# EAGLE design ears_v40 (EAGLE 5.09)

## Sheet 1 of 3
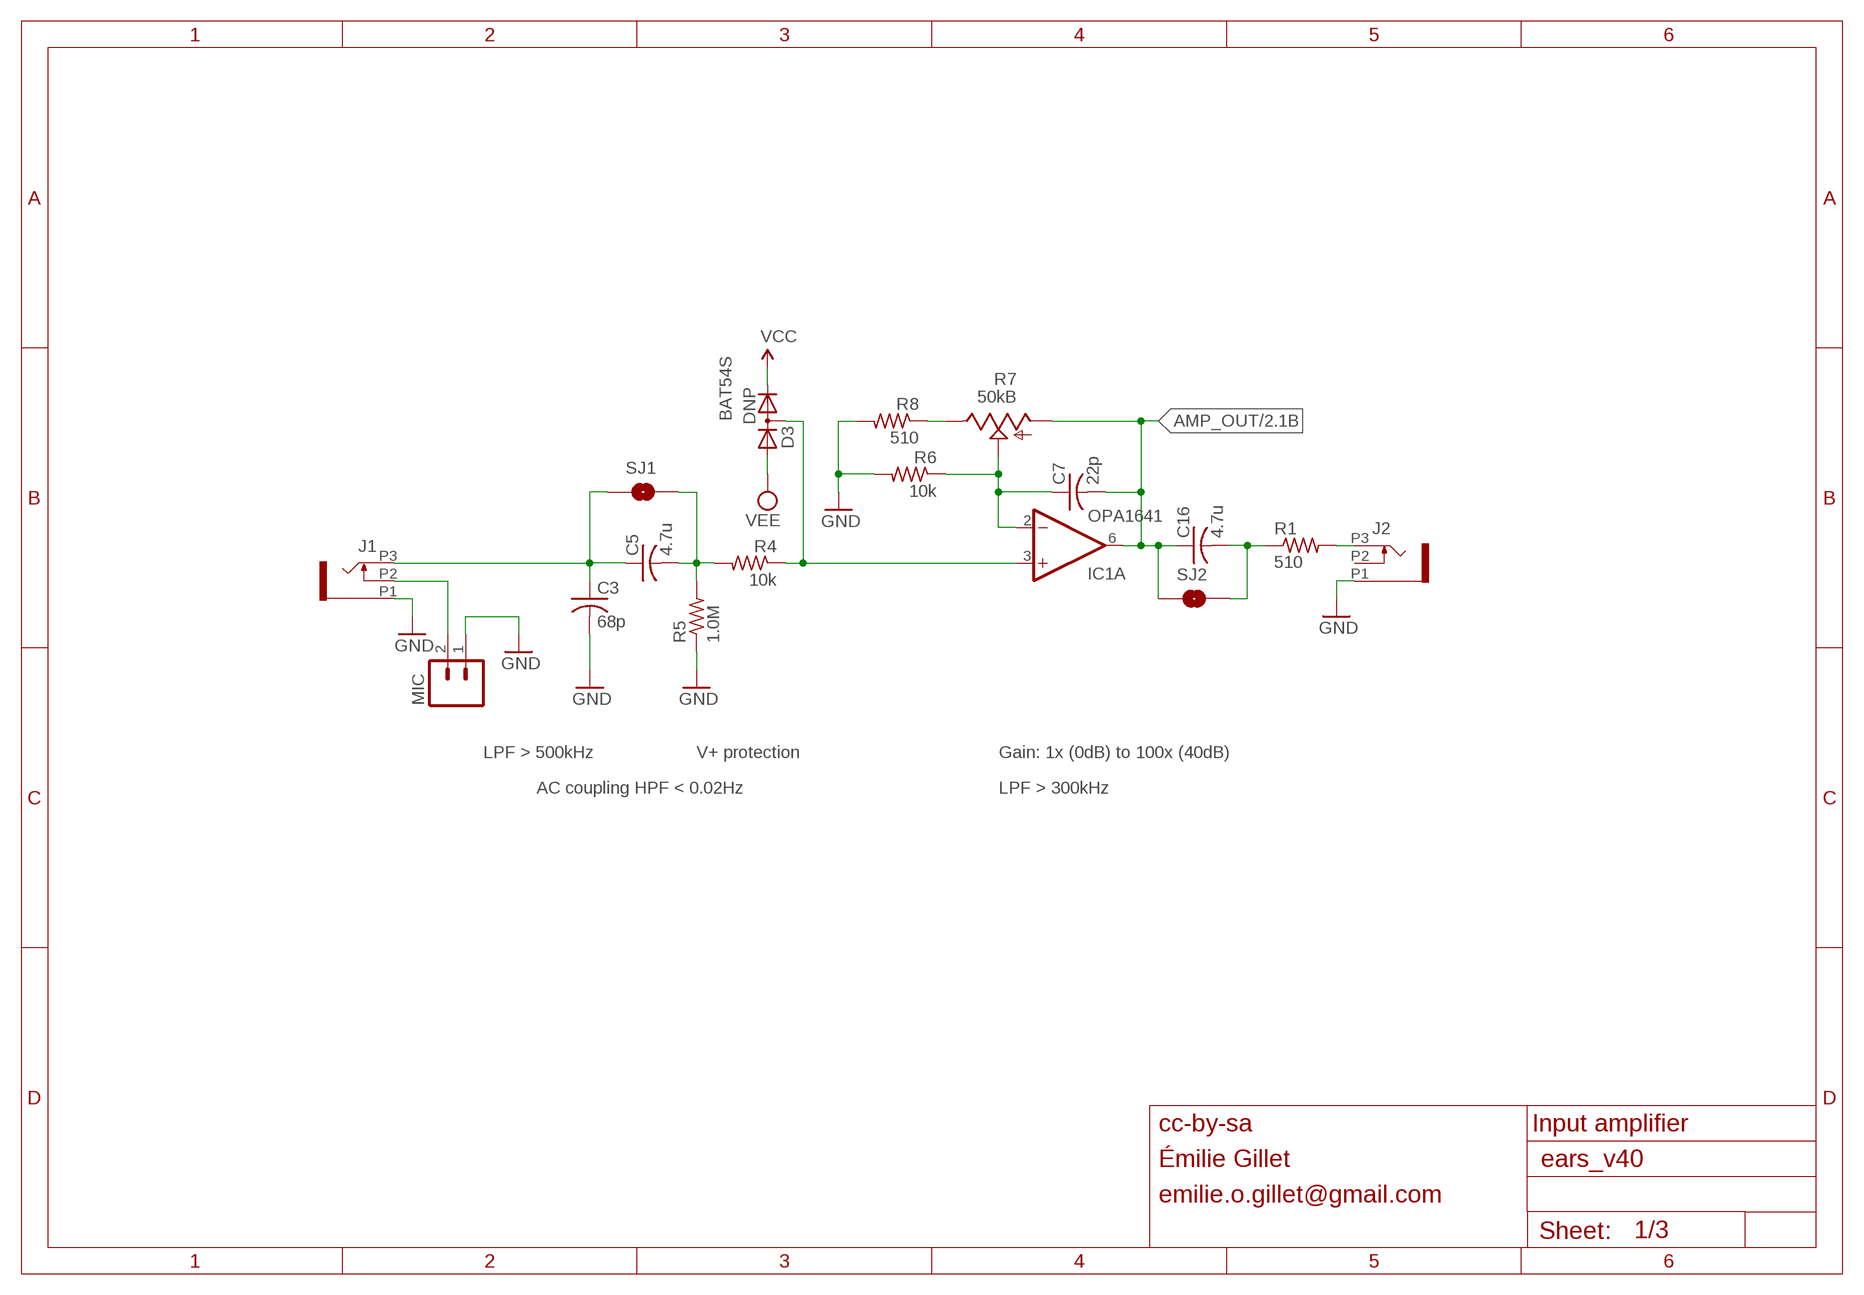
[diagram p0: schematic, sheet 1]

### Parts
C3  68p  C-USC0402  [C0402]
C5  4.7u  C-USC0603  [C0603]
C7  22p  C-USC0402  [C0402]
C16  4.7u  C-USC0603  [C0603]
D3  DNP  DIODE_2CACA-SOT23  [SOT23]
IC1  OPA1641  [MSOP8]
J1  PJ301_THONKICONN6  [WQP_PJ_301M6]
J2  PJ301_THONKICONN6  [WQP_PJ_301M6]
MIC  M02TINY  [1X02_TINY]
R1  510  R-US_R0402  [R0402]
R4  10k  R-US_R0402  [R0402]
R5  1.0M  R-US_R0402  [R0402]
R6  10k  R-US_R0402  [R0402]
R7  50kB  POT_USVERTICAL_PS  [ALPS_POT_VERTICAL_PS]
R8  510  R-US_R0402  [R0402]
SJ1  SOLDERJUMPERNC  [SJ_2S]
SJ2  SOLDERJUMPERNC  [SJ_2S]

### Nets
AMP_OUT: C7.2 C16.1 IC1.6(A:OUT) R7.P$3(A) SJ2.1 ; also sheet 2
GND: C3.2 J1.P1 J2.P1 MIC.1 R5.1 R6.2 R8.2 ; also sheet 2,3
N$2: D3.3(AC) IC1.3(A:+IN) R4.1
N$3: J2.P3 R1.2
N$4: C3.1 C5.1 J1.P3 SJ1.1
N$7: J1.P2 MIC.2
N$9: C7.1 IC1.2(A:-IN) R6.1 R7.P$2(S)
N$10: C5.2 R4.2 R5.2 SJ1.2
N$13: R7.P$1(E) R8.1
N$15: C16.2 R1.1 SJ2.2
VCC: D3.2(C) ; also sheet 2,3
VEE: D3.1(A) ; also sheet 2,3
Unconnected: J2.P2

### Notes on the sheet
- BAT54S
- LPF > 500kHz | V+ protection | Gain: 1x (0dB) to 100x (40dB)
- AC coupling HPF < 0.02Hz | LPF > 300kHz
- cc-by-sa | Input amplifier
- Émilie Gillet
- emilie.o.gillet@gmail.com

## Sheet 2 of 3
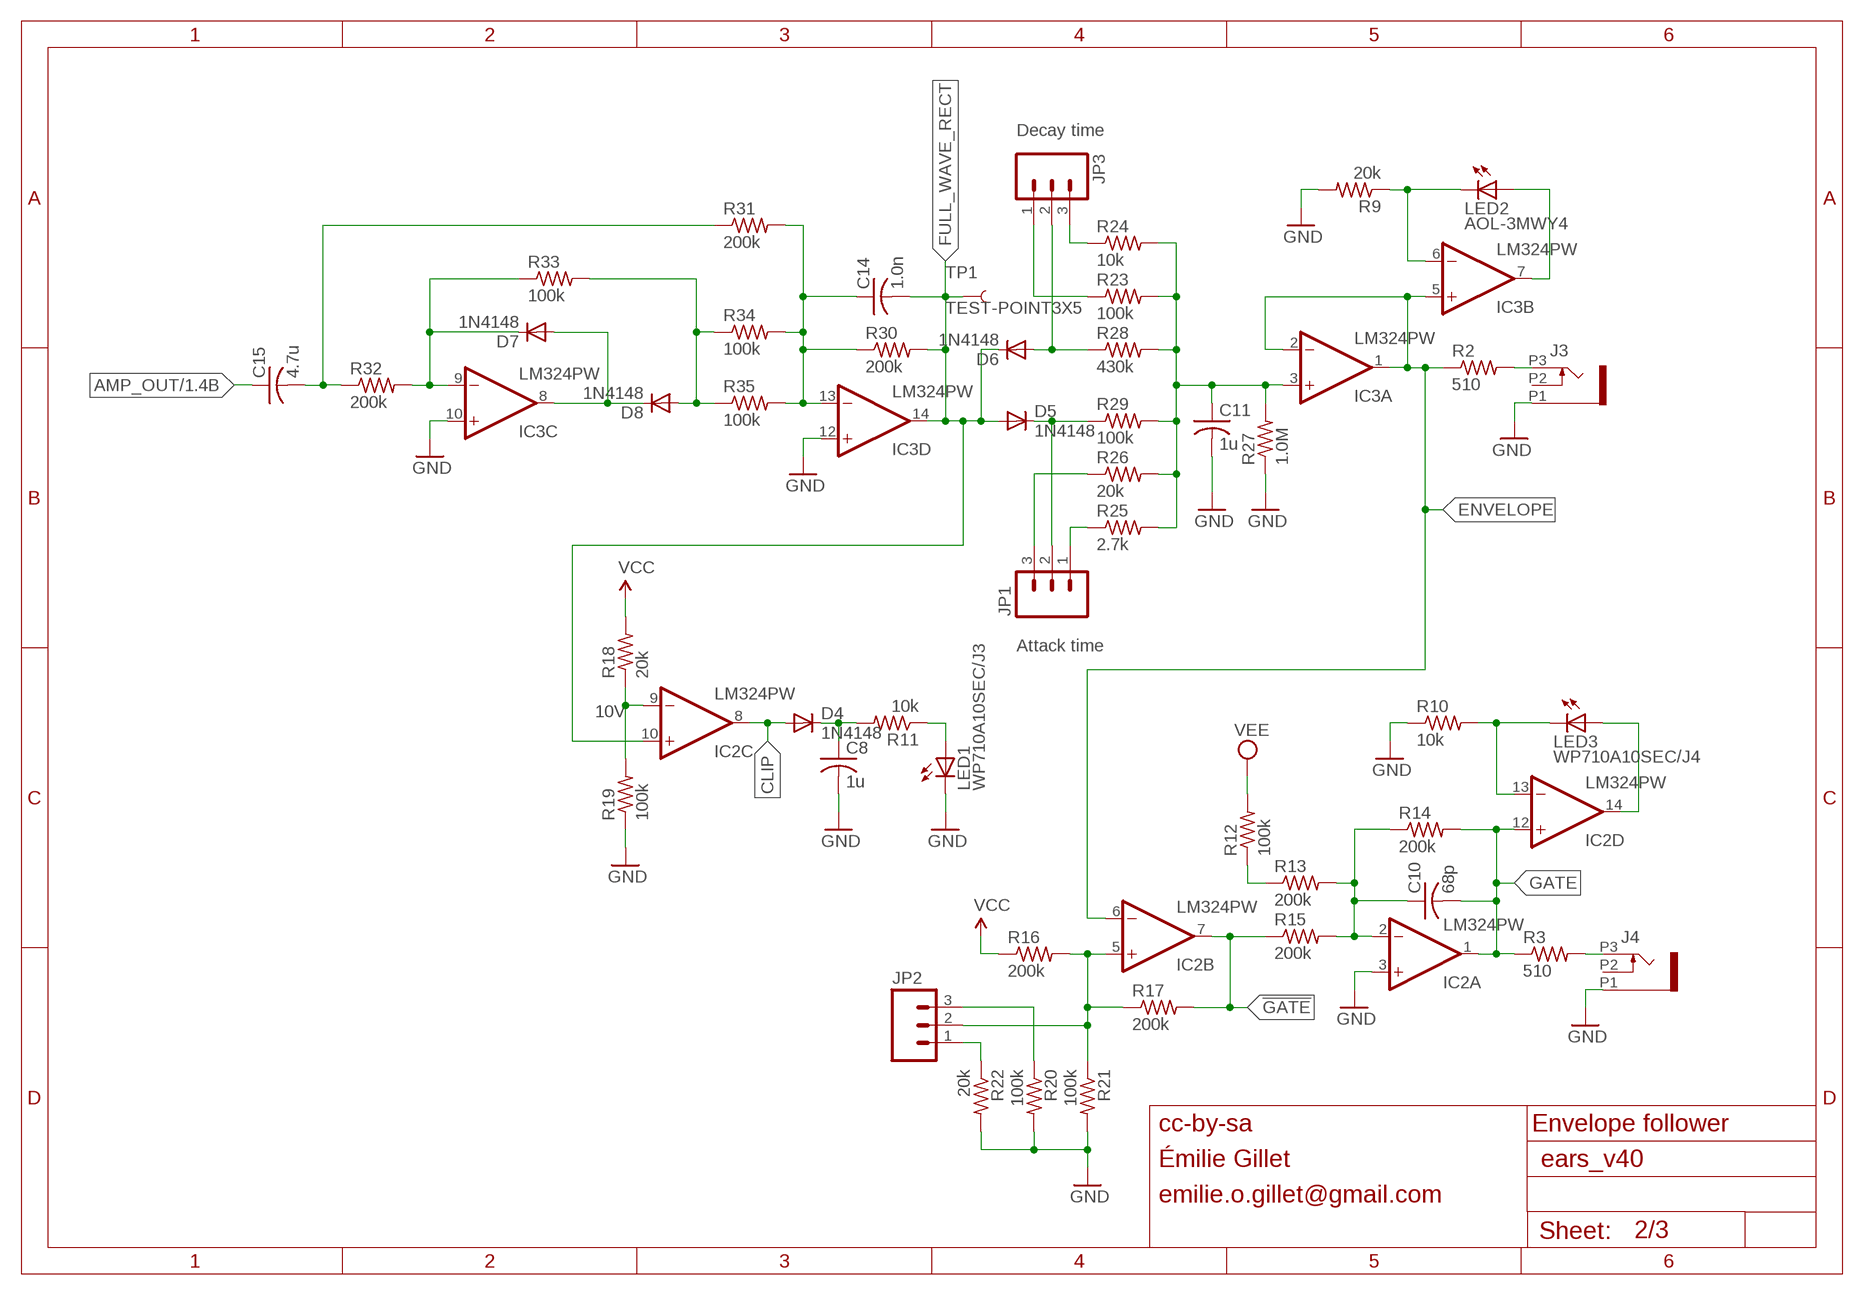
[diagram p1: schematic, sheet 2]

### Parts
C8  1u  C-USC0402  [C0402]
C10  68p  C-USC0402  [C0402]
C11  1u  C-USC0402  [C0402]
C14  1.0n  C-USC0402  [C0402]
C15  4.7u  C-USC0603  [C0603]
D4  1N4148  DIODE-SOD523  [SOD523]
D5  1N4148  DIODE-SOD523  [SOD523]
D6  1N4148  DIODE-SOD523  [SOD523]
D7  1N4148  DIODE-SOD523  [SOD523]
D8  1N4148  DIODE-SOD523  [SOD523]
IC2  LM324PW  [TSSOP14]
IC3  LM324PW  [TSSOP14]
J3  PJ301_THONKICONN6  [WQP_PJ_301M6]
J4  PJ301_THONKICONN6  [WQP_PJ_301M6]
JP1  M03PTH  [1X03]
JP2  M03PTH  [1X03]
JP3  M03PTH  [1X03]
LED1  WP710A10SEC/J3  LED3MM  [LED3MM]
LED2  AOL-3MWY4  LED3MM  [LED3MM]
LED3  WP710A10SEC/J4  LED3MM  [LED3MM]
R2  510  R-US_R0402  [R0402]
R3  510  R-US_R0402  [R0402]
R9  20k  R-US_R0402  [R0402]
R10  10k  R-US_R0402  [R0402]
R11  10k  R-US_R0402  [R0402]
R12  100k  R-US_R0402  [R0402]
R13  200k  R-US_R0402  [R0402]
R14  200k  R-US_R0402  [R0402]
R15  200k  R-US_R0402  [R0402]
R16  200k  R-US_R0402  [R0402]
R17  200k  R-US_R0402  [R0402]
R18  20k  R-US_R0402  [R0402]
R19  100k  R-US_R0402  [R0402]
R20  100k  R-US_R0402  [R0402]
R21  100k  R-US_R0402  [R0402]
R22  20k  R-US_R0402  [R0402]
R23  100k  R-US_R0402  [R0402]
R24  10k  R-US_R0402  [R0402]
R25  2.7k  R-US_R0402  [R0402]
R26  20k  R-US_R0402  [R0402]
R27  1.0M  R-US_R0402  [R0402]
R28  430k  R-US_R0402  [R0402]
R29  100k  R-US_R0402  [R0402]
R30  200k  R-US_R0402  [R0402]
R31  200k  R-US_R0402  [R0402]
R32  200k  R-US_R0402  [R0402]
R33  100k  R-US_R0402  [R0402]
R34  100k  R-US_R0402  [R0402]
R35  100k  R-US_R0402  [R0402]
TP1  TEST-POINT3X5  [PAD.03X.05]

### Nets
!GATE: IC2.7(B:OUT) R15.1 R17.2
AMP_OUT: C15.1 ; also sheet 1
AMP_OUT_AC: C15.2 R31.1 R32.1
CLIP: D4.A IC2.8(C:OUT)
ENVELOPE: IC2.6(B:-IN) IC3.1(A:OUT) IC3.2(A:-IN) IC3.5(B:+IN) R2.1
FULL_WAVE_RECT: C14.2 D5.A D6.C IC2.10(C:+IN) IC3.14(D:OUT) R30.2 TP1.P$1
GATE: C10.2 IC2.1(A:OUT) IC2.12(D:+IN) R3.1 R14.2
GND: C8.2 C11.2 IC2.3(A:+IN) IC3.10(C:+IN) IC3.12(D:+IN) J3.P1 J4.P1 LED1.K(C) R9.2 R10.1 R19.1 R20.2 R21.2 R22.2 R27.1 ; also sheet 1,3
N$5: D7.A D8.C IC3.8(C:OUT)
N$8: C10.1 IC2.2(A:-IN) R13.2 R14.1 R15.2
N$11: D7.C IC3.9(C:-IN) R32.2 R33.1
N$12: D8.A R33.2 R34.1 R35.1
N$14: C14.1 IC3.13(D:-IN) R30.1 R31.2 R34.2 R35.2
N$16: J3.P3 R2.2
N$17: IC3.6(B:-IN) LED2.K(C) R9.1
N$18: D5.C JP1.2 R29.1
N$19: C11.1 IC3.3(A:+IN) R23.2 R24.2 R25.2 R26.2 R27.2 R28.2 R29.2
N$21: JP3.3 R24.1
N$23: JP3.1 R23.1
N$24: D6.A JP3.2 R28.1
N$25: JP1.1 R25.1
N$26: JP1.3 R26.1
N$27: IC2.9(C:-IN) R18.1 R19.2
N$28: C8.1 D4.C R11.2
N$30: IC3.7(B:OUT) LED2.A
N$31: LED1.A R11.1
N$32: J4.P3 R3.2
N$33: IC2.5(B:+IN) JP2.2 R16.2 R17.1 R21.1
N$35: JP2.1 R22.1
N$36: JP2.3 R20.1
N$37: IC2.13(D:-IN) LED3.K(C) R10.2
N$38: IC2.14(D:OUT) LED3.A
N$39: R12.1 R13.1
VCC: R16.1 R18.2 ; also sheet 1,3
VEE: R12.2 ; also sheet 1,3
Unconnected: J3.P2 J4.P2

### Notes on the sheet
- Decay time
- Attack time
- 10V
- cc-by-sa | Envelope follower
- Émilie Gillet
- emilie.o.gillet@gmail.com

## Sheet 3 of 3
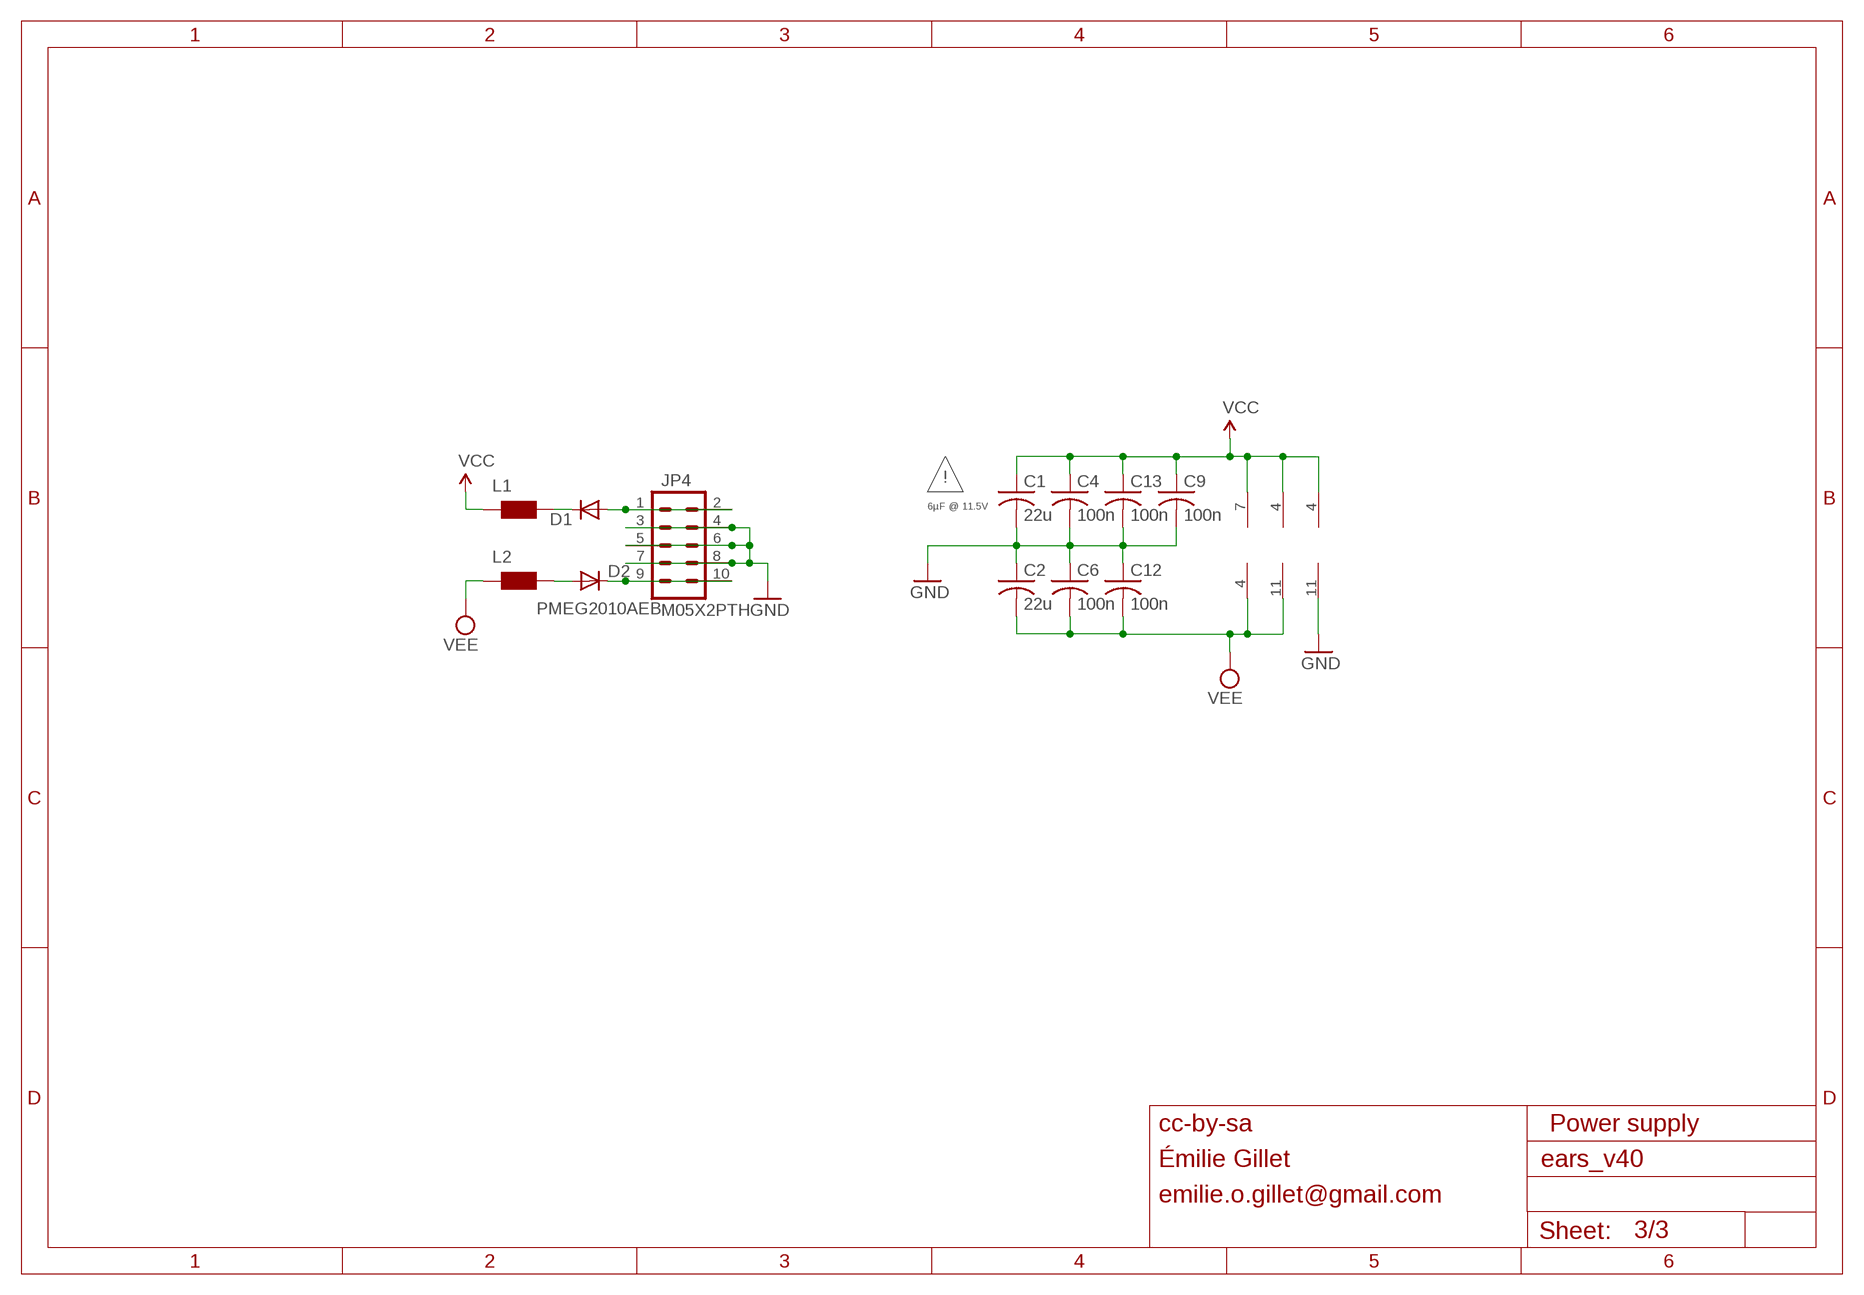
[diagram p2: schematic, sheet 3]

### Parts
C1  22u  C-USC1206  [C1206]
C2  22u  C-USC1206  [C1206]
C4  100n  C-USC0402  [C0402]
C6  100n  C-USC0402  [C0402]
C9  100n  C-USC0402  [C0402]
C12  100n  C-USC0402  [C0402]
C13  100n  C-USC0402  [C0402]
D1  PMEG2010AEB  DIODE-SOD523  [SOD523]
D2  PMEG2010AEB  DIODE-SOD523  [SOD523]
JP4  M05X2PTH  [AVR_ICSP]
L1  WE-CBF_0603  [0603]
L2  WE-CBF_0603  [0603]

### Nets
GND: C1.2 C2.1 C4.2 C6.1 C9.2 C12.1 C13.2 IC2.11(P:V-) JP4.3 JP4.4 JP4.5 JP4.6 JP4.7 JP4.8 ; also sheet 1,2
N$6: D1.A JP4.1 JP4.2
N$20: D2.C JP4.9 JP4.10
N$22: D1.C L1.2
N$44: D2.A L2.2
VCC: C1.1 C4.1 C9.1 C13.1 IC1.7(V+) IC2.4(P:V+) IC3.4(P:V+) L1.1 ; also sheet 1,2
VEE: C2.2 C6.2 C12.2 IC1.4(V-) IC3.11(P:V-) L2.1 ; also sheet 1,2

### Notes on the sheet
- !
- 6µF @ 11.5V
- cc-by-sa | Power supply
- Émilie Gillet
- emilie.o.gillet@gmail.com

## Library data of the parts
C1-C16 = rcl:C-US: CAPACITOR, American symbol
D1 D2 D4-D8 = diode:DIODE-: DIODE
D3 = diode:DIODE_2CACA-: 2 Diodes - Cathode-Anode|Cathode-Anode
IC1 = og-ics:OPA1641
IC2 IC3 = og-ics:LM324: OP AMP
J1-J4 = og-pj301:PJ301_THONKICONN
JP1-JP3 = SparkFun:M03: Header 3 Standard 3-pin 0.1" header. Use with straight break away headers (SKU : PRT-00116), right angle break away headers (PRT-00553), swiss pins (PRT-00743), machine pins (PRT-00117), and female headers (PRT-00115). Molex polarized connector foot print use with SKU : PRT-08232 with associated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
JP4 = og-header:M05X2: Header 5x2 Standard 10-pin dual row 0.1" header. Commonly used with AVR-ISP. Use with Spark Fun Electronics SKU: PRT-00778
L1 L2 = wuerth-elektronik:WE-CBF: SMD EMI Suppression Ferrite Beads
LED1-LED3 = led:LED: LED
MIC = og-header:M02: Header 2
R1-R6 R8-R35 = rcl:R-US_: RESISTOR, American symbol
R7 = og-pots:POT_US
SJ1 SJ2 = SparkFun:SOLDERJUMPER: Solder Jumper
TP1 = SparkFun:TEST-POINT

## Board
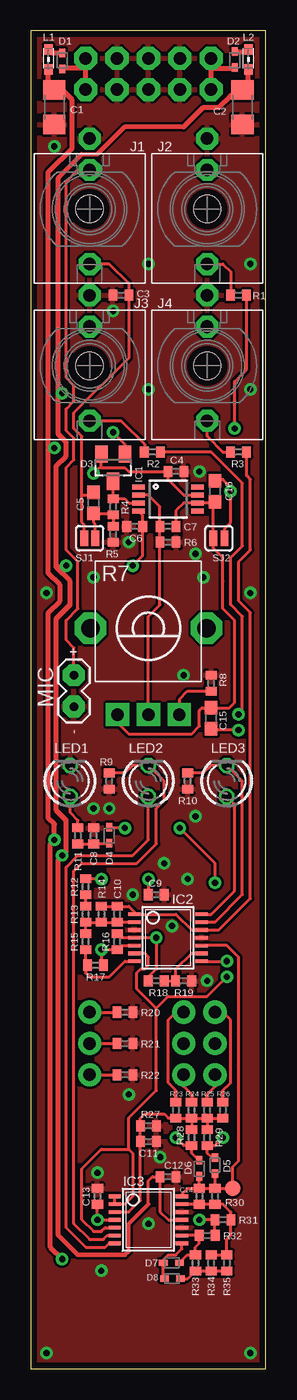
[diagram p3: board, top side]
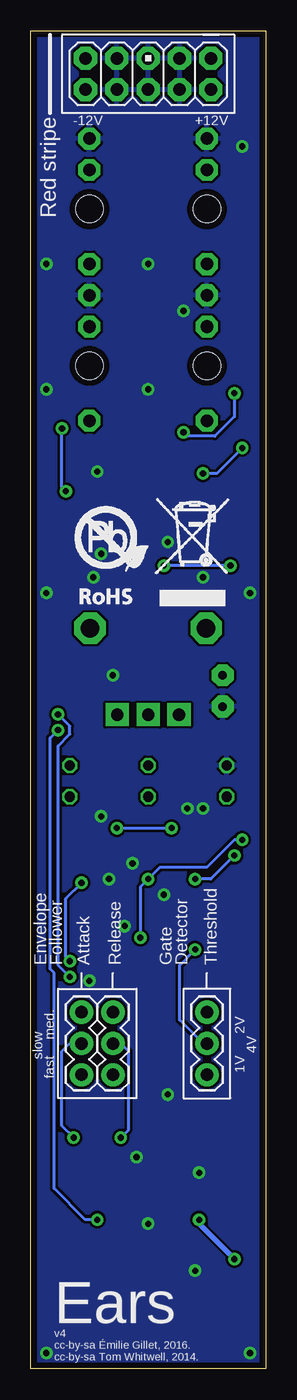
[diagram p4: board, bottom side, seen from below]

Size 19.03 x 108.43 mm. Coordinates in mm from the lower left corner, seen from the top.
Outline: 0,0 19.03,0 19.03,108.43 0,108.43 0,0
Copper layers (1*16): Top 0.035mm / dielectric 1.5mm / Bottom 0.035mm
Design rules "PCBCart-Standard *": minimum track width 8mil, minimum drill 0.4mm, track to track 8mil, track to pad 8mil, pad to pad 8mil, via to via 8mil, smd to smd 8mil, copper to edge 20mil, drill to drill 8mil, minimum pad ring 8mil, minimum via ring 10mil, stop-mask expansion 3mil, vias tented up to drill 25mil, thermal gap 8mil

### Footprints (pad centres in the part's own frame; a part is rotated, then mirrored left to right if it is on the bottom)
C1206 = smd 1.6 x 1.8: 1 -1.4,0; 2 1.4,0
C0402 = smd 0.7 x 0.9: 1 -0.65,0; 2 0.65,0
C0603 = smd 1.1 x 1: 1 -0.85,0; 2 0.85,0
SOD523 = smd 0.7 x 0.5: A 0.7,0; C -0.6,0
SOT23 = smd 1 x 1.4: 1 -0.95,-1.1; 2 0.95,-1.1; 3 0,1.1
MSOP8 = smd 0.41 x 1.02: 1 -0.975,-2.4; 2 -0.325,-2.4; 3 0.325,-2.4; 4 0.975,-2.4; 5 0.975,2.4; 6 0.325,2.4; 7 -0.325,2.4; 8 -0.975,2.4
TSSOP14 = smd 0.305 x 0.991: 1 -1.905,-2.718; 2 -1.27,-2.718; 3 -0.635,-2.718; 4 0,-2.718; 5 0.635,-2.718; 6 1.27,-2.718; 7 1.905,-2.718; 8 1.905,2.718; 9 1.27,2.718; 10 0.635,2.718; 11 0,2.718; 12 -0.635,2.718; 13 -1.27,2.718; 14 -1.905,2.718
WQP_PJ_301M6 = drill 1.016 pad 1.778 octagon: P1 0,-5.715; P2 0,-3.175; P3 0,4.445 | hole 2.2: 0,0
1X03 = drill 1.016 pad 1.88 round: 1 0,0; 2 2.54,0; 3 5.08,0
AVR_ICSP = drill 1.016 pad 1.88 octagon: 1 -1.27,5.08; 2 1.27,5.08; 3 -1.27,2.54; 4 1.27,2.54; 5 -1.27,0; 6 1.27,0; 7 -1.27,-2.54; 8 1.27,-2.54; 9 -1.27,-5.08; 10 1.27,-5.08
0603 = smd 0.85 x 0.7: 1 -0.9,0; 2 0.7,0
LED3MM = drill 0.813 octagon: A -1.27,0; K 1.27,0
1X02_TINY = drill 0.7 pad 1.778 octagon: 1 0,0; 2 2.54,0
R0402 = smd 0.7 x 0.9: 1 -0.65,0; 2 0.65,0
ALPS_POT_VERTICAL_PS = drill 1 pad 1.88 square: P$1 -2.5,7; P$2 0,7; P$3 2.5,7 | drill 1.5 pad 2.54 octagon: P$4 -4.7,0; P$5 4.7,0
SJ_2S = smd 0.635 x 1.27: 1 -0.45,0; 2 0.45,0
PAD.03X.05 = smd 1.27 x 1.27: P$1 0,0

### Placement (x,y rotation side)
C1  1.91,102.23 270 top
C2  17.14,102.23 90 top
C3  7.3,87 180 top
C4  11.75,72.71 0 top
C5  5.08,70.17 270 top
C6  8.41,68.26 0 top
C7  11.11,68.26 0 top
C8  5.08,43.18 90 top
C9  10.16,38.42 0 top
C10  6.99,36.83 90 top
C11  9.53,18.41 0 top
C12  11.11,15.56 180 top
C13  5.4,13.97 90 top
C14  13.65,13.97 90 top
C15  14.61,52.7 270 top
C16  14.92,71.12 90 top
D1  2.54,106.05 270 top
D2  16.51,106.05 90 top
D3  6.67,73.03 180 top
D4  6.35,43.18 90 top
D5  14.92,16.51 270 top
D6  13.65,16.19 90 top
D7  11.43,8.57 180 top
D8  11.43,7.3 0 top
IC1  11.11,70.48 270 top
IC2  11.11,34.92 270 top
IC3  9.53,12.06 270 top
J1  4.76,93.98 180 top
J2  14.29,93.98 180 top
J3  4.76,81.28 180 top
J4  14.29,81.28 180 top
JP1  14.92,23.81 90 bottom
JP2  4.76,23.81 90 bottom
JP3  12.38,28.89 270 bottom
JP4  9.53,104.93 270 bottom
L1  1.43,106.2 90 top
L2  17.62,106.2 90 top
LED1  3.17,47.62 90 top
LED2  9.53,47.62 90 top
LED3  15.88,47.62 90 top
MIC  3.49,53.66 90 top
R1  16.83,87 180 top
R2  9.84,74.3 180 top
R3  16.83,74.3 180 top
R4  6.67,69.85 270 top
R5  6.67,67.63 90 top
R6  11.11,66.99 0 top
R7  9.53,60.01 180 top
R8  14.61,55.56 90 top
R9  6.35,47.62 270 top
R10  12.7,47.62 90 top
R11  3.81,43.18 270 top
R12  4.45,39.05 90 top
R13  4.45,36.83 270 top
R14  5.71,36.83 90 top
R15  4.45,34.61 90 top
R16  6.99,34.61 270 top
R17  5.24,32.7 180 top
R18  10.16,31.43 180 top
R19  12.38,31.43 180 top
R20  7.62,28.89 0 top
R21  7.62,26.35 0 top
R22  7.62,23.81 0 top
R23  11.75,20.95 270 top
R24  13.02,20.95 270 top
R25  14.29,20.95 270 top
R26  15.56,20.95 270 top
R27  9.53,19.68 180 top
R28  13.02,18.73 90 top
R29  14.29,18.73 90 top
R30  14.92,13.97 90 top
R31  15.56,12.06 0 top
R32  14.29,10.79 180 top
R33  13.34,8.57 270 top
R34  14.61,8.57 90 top
R35  15.88,8.57 90 top
SJ1  4.76,67.31 0 top
SJ2  15.24,67.31 0 top
TP1  16.35,14.61 0 top
U$2  [ROHS]  16.35,61.28 0 bottom

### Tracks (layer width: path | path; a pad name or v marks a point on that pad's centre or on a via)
!GATE
  Top 0.254: R15.1 4.45,32.85 R17.2 4.45,32.56 4.45,32.07 4.76,31.75 6.35,31.75 7.62,33.02 IC2.7
AMP_OUT
  Top 0.254: R7.P$3 6.99,52.97 6.99,52.39 7.94,51.44 13.02,51.44 13.65,52.07 13.65,53.34 13.87,53.55 C15.1 16.09,53.55 16.51,53.98 16.51,60.64 15.56,61.59 15.56,63.82 15.56,65.72 14.79,66.49 SJ2.1 14.79,70.14 14.82,70.17 | C7.2 11.75,68.28 11.75,69.53 12.38,70.16 IC1.6 14.82,70.17 | 14.82,70.17 C16.1
AMP_OUT_AC  (via drill 0.5)
  Top 0.254: R31.1 14.92,12.05 | R32.1 14.91,10.82 R31.1 | R31.1 v13.65,12.06 | C15.2 14.71,51.75 v16.83,51.75
  Bottom 0.254: v16.83,51.75 17.46,51.12 17.46,32.38 17.14,32.07 17.14,14.61 14.61,12.06 v13.65,12.06
CLIP  (via drill 0.5)
  Top 0.254: IC2.8 v15.88,33.02 | D4.A 6.42,43.81 v7.62,43.81 | v12.06,43.81 14.92,40.96 v14.92,39.37
  Bottom 0.254: v15.88,33.02 16.19,33.34 16.19,38.1 v14.92,39.37 | v12.06,43.81 v7.62,43.81
ENVELOPE  (via drill 0.5)
  Top 0.254: 6.67,11.43 IC3.5 6.03,11.43 5.71,11.11 5.08,11.11 4.13,12.06 4.13,16.19 5.71,17.78 7.94,17.78 | v15.88,31.75 14.29,30.16 11.11,30.16 10.16,29.21 | IC2.6 9.21,33.66 9.53,33.34 9.53,32.7 9.21,32.38 8.89,32.38 8.57,32.07 8.57,30.8 10.16,29.21 | IC3.1 IC3.2 7.62,13.34 8.26,13.97 8.26,17.46 7.94,17.78 | v16.83,53.02 17.14,53.34 17.14,60.96 16.19,61.91 16.19,65.72 17.14,66.67 17.14,71.75 15.56,73.34 14.61,74.3 R2.1 | 7.94,17.78 7.94,20.32 10.16,22.54 10.16,29.21
  Bottom 0.254: v16.83,53.02 15.88,52.07 15.88,51.44 16.83,50.48 16.83,32.7 v15.88,31.75
FULL_WAVE_RECT
  Top 0.254: C14.2 13.64,14.61 12.7,14.61 12.24,14.15 IC3.14 | C14.2 R30.2 | C14.2 D6.C | R30.2 D5.A | R30.2 14.94,14.61 TP1.P$1 16.35,16.35 16.83,16.83 16.83,33.34 15.88,34.29 IC2.10
GATE
  Top 0.254: R14.2 C10.2 7,37.47 7.94,37.47 8.39,37.01 IC2.1 11.75,36.83 13.02,35.56 IC2.12 15.24,35.56 17.78,38.1 17.78,61.28 16.83,62.23 16.83,65.41 17.78,66.36 17.78,72.07 17.48,72.38 R3.1
GND  (via drill 0.5)
  other vias: 5.4,15.88 5.71,7.94 13.97,64.14 13.65,72.71 7.94,66.99 14.29,31.43 10.48,17.14 12.7,39.69 9.53,11.75 1.91,99.06 6.35,45.4 13.34,44.77 1.27,62.87 7.94,22.23 5.08,45.4 12.38,56.2 17.78,1.27 1.27,1.27 17.78,62.87 5.08,64.14 8.26,38.42 10.79,40.96 11.43,35.88 17.78,89.53 17.78,79.38 9.53,89.53 9.53,79.38 13.34,66.04 6.67,85.72
  pour Bottom: 0,108.43 0,0 19.05,0 19.05,108.43
  pour Top: 0,108.43 0,0 19.05,0 19.05,108.43
N$2
  Top 0.254: IC1.3 | IC1.3 7.94,70.17 7.61,70.5 R4.1 D3.3
N$3
  Top 0.254: J2.P3 15.56,89.53 16.18,88.92 R1.2
N$4
  Top 0.254: J1.P3 6.35,89.53 7.95,87.93 C3.1 7.95,81.93 3.49,77.47 3.49,76.2 4.13,75.56 4.13,70.8 | 4.13,70.8 4.13,68.58 4.31,68.39 SJ1.1 | C5.1 4.87,70.8 4.13,70.8
N$5
  Top 0.254: D8.C 10.73,7.4 D7.A 10.79,8.64 10.79,8.89 11.11,9.21 11.75,9.21 12.24,9.7 IC3.8
N$6
  Top 0.406: JP4.2 4.45,105.41 | 4.45,105.41 JP4.1 | D1.A 2.6,105.41 4.45,105.41
N$7
  Top 0.254: MIC.2 3.49,58.42 2.86,59.05 2.86,60.64 3.81,61.59 3.81,65.41 2.86,66.36 2.86,73.03 3.49,73.66 3.49,75.41 2.86,76.04 2.86,77.79 3.49,78.42 3.49,79.69 2.86,80.33 2.86,80.64 2.86,96.2 3.81,97.16 J1.P2
N$8
  Top 0.254: IC2.2 7,36.2 C10.1 R14.1 R13.2 R15.2
N$9
  Top 0.254: R7.P$2 9.53,60.96 10.46,61.9 R6.1 C7.1 10.46,69.86 9.53,70.8 IC1.2
N$10
  Top 0.254: SJ1.2 5.21,68.45 5.08,68.58 C5.2 6.55,69.32 R4.2 R5.2
N$11
  Top 0.254: IC3.9 R32.2 13.64,10.14 13.34,9.84 R33.1 12.68,9.22 D7.C
N$12
  Top 0.254: R35.1 R34.1 R33.2 13.32,7.92 12.7,7.3 D8.A
N$13
  Top 0.254: R7.P$1 12.06,53.05 12.06,54.29 12.69,54.91 R8.1
N$14
  Top 0.254: IC3.13 13.64,13.34 C14.1 R30.1 14.94,13.34 15.56,13.34 16.21,12.69 R31.2 16.21,10.81 15.88,10.48 R35.2 R34.2
N$15  (via drill 0.5)
  Top 0.254: C16.2 15.03,72.07 15.56,72.07 16.19,71.44 v16.19,71.12 16.19,68.58 15.69,68.08 SJ2.2 | v16.51,76.2 16.51,80.01 17.48,80.98 R1.1
  Bottom 0.254: v16.19,71.12 16.51,71.44 v16.51,76.2
N$16
  Top 0.254: 9.21,74.31 R2.2 9.21,74.31 | 9.21,74.31 9.21,74.93 7.3,76.83 J3.P3
N$17
  Top 0.254: IC3.6 6.19,10.79 5.87,10.48 4.76,10.48 3.49,11.75 3.49,40.32 4.13,40.96 8.57,40.96 10.16,42.55 10.16,45.4 10.79,46.04 10.79,47.62 LED2.K 8.26,48.9 7.62,48.26 6.37,48.26 R9.1
N$18  (via drill 0.5)
  Top 0.254: D5.C 14.64,17.11 14.29,17.46 R29.1 14.3,18.1 14.92,18.1 v15.56,18.73
  Bottom 0.254: v15.56,18.73 16.51,19.68 16.51,25.72 15.88,26.35 JP1.2
N$19
  Top 0.254: R24.2 R23.2 11.73,20.32 11.11,20.32 10.79,20.64 9.21,20.64 8.88,20.3 R27.2 C11.1 8.88,13.64 7.94,12.7 IC3.3 | R24.2 R28.2 | R24.2 R25.2 | R25.2 R26.2 | R25.2 R29.2
N$20
  Top 0.406: JP4.10 14.61,105.41 | 14.61,105.41 JP4.9 | D2.C 16.48,105.41 14.61,105.41
N$21
  Top 0.254: JP3.3 12.38,22.86 13.02,22.23 R24.1
N$22
  Top 0.406: L1.2 1.69,106.64 D1.C
N$23
  Top 0.254: JP3.1 11.75,28.89 11.11,28.26 11.11,23.18 11.75,22.54 R23.1
N$24  (via drill 0.5)
  Top 0.254: D6.A 13.59,16.89 13.02,17.46 R28.1 13,18.1 12.38,18.1 v11.75,18.73
  Bottom 0.254: v11.75,18.73 11.11,19.37 11.11,25.72 11.75,26.35 JP3.2
N$25
  Top 0.254: JP1.1 14.92,22.86 14.29,22.23 R25.1
N$26
  Top 0.254: JP1.3 15.56,28.89 16.19,28.26 16.19,23.18 15.56,22.54 R26.1
N$27
  Top 0.254: R18.1 R19.2 11.75,31.45 11.75,32.38 13.02,33.66 IC2.9
N$28
  Top 0.254: R11.2 C8.1 5.13,42.58 D4.C
N$30
  Top 0.254: IC3.7 6.35,10.16 6.03,9.84 4.45,9.84 2.86,11.43 2.86,40.64 3.81,41.59 8.26,41.59 9.53,42.86 LED2.A
N$31
  Top 0.254: LED1.A 3.17,45.09 3.81,44.45 R11.1
N$32
  Top 0.254: J4.P3 14.29,75.56 15.56,74.3 R3.2
N$33  (via drill 0.5)
  Top 0.254: JP2.2 R21.1 | IC2.5 7.32,34.29 R16.2 6.97,33.97 v5.71,33.97 5.71,32.88 R17.1
  Bottom 0.254: v5.71,33.97 6.99,32.7 6.99,28.26 5.08,26.35 JP2.2
N$35
  Top 0.254: JP2.1 R22.1
N$36
  Top 0.254: JP2.3 R20.1
N$37
  Top 0.254: IC2.13 14.92,36.2 17.14,38.42 17.14,47.62 LED3.K 14.61,48.9 13.97,48.26 12.71,48.26 R10.2
N$38
  Top 0.254: IC2.14 14.61,36.83 16.51,38.73 16.51,45.72 LED3.A
N$39
  Top 0.254: R13.1 R12.1
N$44
  Top 0.406: L2.2 17.46,106.75 D2.A
VCC  (via drill 0.5)
  Top 0.254: R16.1 7.32,34.92 IC2.4 v10.16,34.92 10.16,32.38 9.53,31.75 9.53,31.45 R18.2 | v9.53,39.69 9.51,39.67 C9.1 | IC3.4 v5.4,12.06 C13.1 | IC1.7 12.38,70.8 11.1,72.09 C4.1 7.94,72.71 7.62,73.03 5.71,73.03 | v5.08,72.55 5.56,73.03 5.71,73.03 | D3.2 5.71,73.03
  Top 0.406: L1.1 1.43,103.98 1.59,103.82 1.72,103.82 C1.1 2.54,103.64 3.33,102.84 3.33,98.9 1.43,97 1.43,74.61 | 1.43,74.61 v1.91,74.61 | 1.43,74.61 1.43,64.45 2.38,63.5 2.38,62.23 1.43,61.28 1.43,44.61 1.91,44.13 v1.91,42.86 1.59,42.55 1.59,9.84 v2.54,8.89
  Bottom 0.254: v1.91,74.61 3.97,72.55 4.13,72.55 v5.08,72.55 | v1.91,42.86 2.54,42.86 4.76,40.64 8.57,40.64 v9.53,39.69 10.16,39.05 v10.16,34.92
  Bottom 0.406: v2.54,8.89 5.4,11.75 v5.4,12.06
VEE  (via drill 0.5)
  Top 0.254: C12.2 10.48,15.57 | C12.2 10.48,15.54 | v5.71,39.69 5.7,39.7 R12.2 | v8.26,65.09 8.75,65.58 9.06,65.9 C6.2 | 2.06,65.09 v2.86,65.09 | 9.53,13.34 9.53,15.24 9.84,15.56 C12.2 | IC3.11 11.11,12.06 10.46,12.71 C12.2 | C6.2 8.89,68.44 | 2.22,79.06 v2.54,79.06 | IC1.4 9.06,69.16 C6.2 | v6.67,75.88 7.62,74.93 D3.1
  Top 0.305: 7.62,9.21 7.94,9.53 7.94,11.75 9.53,13.34 | 4.13,98.42 5.4,98.42
  Top 0.356: 3.81,9.21 7.62,9.21 | 2.22,96.52 4.13,98.42 | 5.4,98.42 7.62,100.65
  Top 0.381: 7.62,100.65 12.38,100.65 | 3.81,9.21 2.22,10.79
  Top 0.406: L2.1 17.62,103.98 17.46,103.82 17.33,103.82 C2.2 17.14,103.19 16.19,103.19 15.24,102.23 13.97,102.23 12.38,100.65 | 2.22,10.79 2.22,41.27 v2.54,41.59 2.86,41.91 2.86,44.45 2.06,45.24 2.06,60.8 3.17,61.91 3.17,63.82 2.06,64.93 2.06,65.09 2.06,73.18 2.86,73.98 2.86,75.09 2.22,75.72 2.22,79.06 2.22,96.52
  Bottom 0.254: v2.86,65.09 v8.26,65.09 | v2.54,41.59 4.45,39.69 v5.71,39.69 | v2.54,79.06 2.54,77.15 4.13,75.56 6.35,75.56 v6.67,75.88

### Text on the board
tPlace: + | -
bPlace: Red stripe | Threshold | Detector | Gate | Release | Attack | Follower | Envelope | 2V | 4V | med. | 1V | slow | fast
bNames: +12V | -12V | Ears | v4 | cc-by-sa Émilie Gillet, 2016. | cc-by-sa Tom Whitwell, 2014.
tDocu: DC IN | DC OUT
